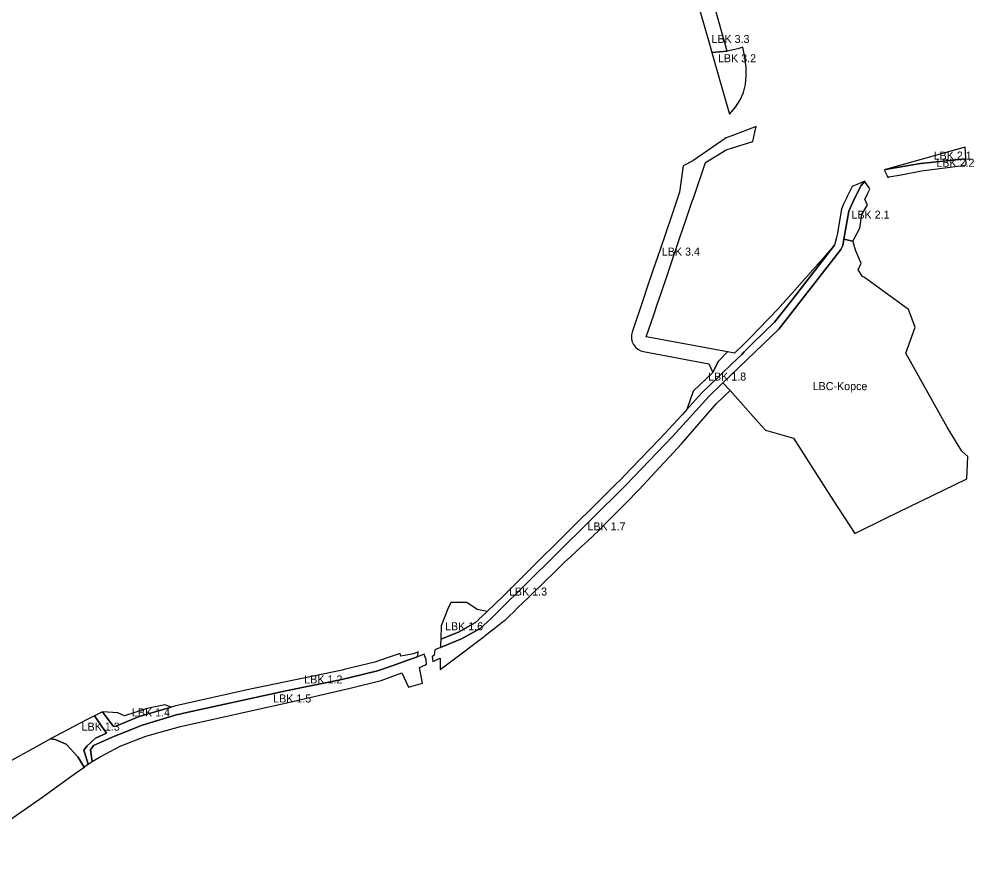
# Model space of a CAD drawing. Extents: x -535894 to -532748, y -1165802 to -1163647.
# Drawn here: x -534673 to -533719, y -1165546 to -1164715 of the extents above; entities that cross this region are included whole.
import ezdxf

# ---------------------------------------------------------------- set-up
doc = ezdxf.new("R2010")
doc.units = 0
for name, color, linetype in [('Level 16', 7, 'Continuous'), ('Level 19', 7, 'Continuous'), ('Level 20', 7, 'Continuous')]:
    doc.layers.add(name, color=color, linetype=linetype)

msp = doc.modelspace()

# ---------------------------------------------------------------- linework, layer by layer
at = {"layer": 'Level 16'}
msp.add_lwpolyline([(-533837.94, -1165228.09), (-533806.07, -1165212.59), (-533726.09, -1165173.68), (-533724.81, -1165151.41), (-533730.88, -1165145.85), (-533745.52, -1165122.1), (-533766.31, -1165084.95), (-533786.95, -1165048.06), (-533777.72, -1165022.03), (-533784.18, -1165004.34), (-533828.25, -1164972.65), (-533830.03, -1164971.49), (-533834.67, -1164964.81), (-533831.57, -1164958.17), (-533833.05, -1164954.72), (-533837.05, -1164945.36), (-533838.84, -1164939.32), (-533839.74, -1164936.26), (-533848.68, -1164934.44), (-533849.69, -1164940.46), (-533851.83, -1164944.65), (-533913.79, -1165024.04), (-533969.7, -1165077.78), (-533962.53, -1165085.32), (-533934.45, -1165116.87), (-533927.15, -1165125.06), (-533899.27, -1165133.08), (-533859.04, -1165195.4)], close=True, dxfattribs=at)
at = {"layer": 'Level 19'}
for points in [[(-533965.28, -1164746.51), (-533980.66, -1164747.97), (-533974.92, -1164767.93), (-533963.1, -1164809.55), (-533956.94, -1164802.51), (-533952.29, -1164795.25), (-533949.05, -1164787.68), (-533947.08, -1164779.74), (-533946.27, -1164771.35), (-533946.51, -1164762.43), (-533947.67, -1164752.91), (-533949.63, -1164742.72), (-533954.82, -1164744.13)], [(-533772.11, -1164858.69), (-533807.19, -1164864.79), (-533808.26, -1164865.36), (-533807.83, -1164866.32), (-533805.67, -1164871.11), (-533804.97, -1164872.65), (-533803.9, -1164872.2), (-533791.44, -1164869.9), (-533771.09, -1164866.14), (-533747.79, -1164863), (-533732.38, -1164860.92), (-533728.63, -1164860.41), (-533726.94, -1164860.18), (-533726.73, -1164859.25), (-533726.9, -1164854), (-533727.16, -1164854.1)], [(-533838.18, -1164893.83), (-533843.98, -1164906.47), (-533848.68, -1164934.44), (-533839.74, -1164936.26), (-533832.91, -1164923.14), (-533831.01, -1164909.18), (-533825.11, -1164900.3), (-533827.81, -1164894.29), (-533825.28, -1164889.29), (-533825.17, -1164889.09), (-533822.83, -1164884.29), (-533823.63, -1164883.1), (-533827.39, -1164877.5), (-533827.73, -1164876.4), (-533831.54, -1164880.79)], [(-533962.53, -1165085.32), (-533969.7, -1165077.78), (-533971.79, -1165079.79), (-533983.52, -1165091.15), (-534019.59, -1165130.92), (-534066.72, -1165179.82), (-534136.8, -1165249.37), (-534194.29, -1165306.12), (-534200.89, -1165312.54), (-534205.31, -1165316.61), (-534212.27, -1165323.02), (-534230.69, -1165333.38), (-534251.77, -1165341.96), (-534257.49, -1165344.29), (-534257.97, -1165349.66), (-534259.96, -1165351.32), (-534259.48, -1165355.88), (-534252.01, -1165352.47), (-534252.23, -1165361.54), (-534251.99, -1165363.99), (-534244.32, -1165358.18), (-534208.23, -1165330.82), (-534207.06, -1165329.91), (-534201.15, -1165325.32), (-534195.4, -1165320.86), (-534189.75, -1165316.48), (-534186.9, -1165314.27), (-534183.78, -1165311.24), (-534178, -1165305.62), (-534174.7, -1165302.41), (-534169.57, -1165297.42), (-534163.98, -1165291.99), (-534158.49, -1165286.65), (-534151.99, -1165280.33), (-534145.91, -1165274.41), (-534140, -1165268.66), (-534133.62, -1165262.47), (-534128.78, -1165257.75), (-534128.1, -1165257.13), (-534121.92, -1165251.44), (-534116.12, -1165246.09), (-534110.88, -1165241.27), (-534105.03, -1165235.88), (-534098.91, -1165230.23), (-534093.73, -1165225.02), (-534088.44, -1165219.7), (-534083.69, -1165214.91), (-534080.31, -1165211.51), (-534069.42, -1165200.54), (-534066.63, -1165197.75), (-534062.36, -1165193.44), (-534057.5, -1165188.56), (-534053.42, -1165184.18), (-534033.26, -1165162.58), (-534022.96, -1165151.54), (-534010.91, -1165138.64), (-533976.02, -1165098.2)], [(-534598.29, -1165439.76), (-534601.36, -1165444.1), (-534599.87, -1165455.71), (-534591.82, -1165451.2), (-534571.82, -1165440.57), (-534546.3, -1165430.52), (-534511.63, -1165420.88), (-534404.04, -1165396.72), (-534341.94, -1165382.62), (-534311.13, -1165374.91), (-534290.38, -1165367.27), (-534283.61, -1165381.53), (-534269.9, -1165377.58), (-534272.9, -1165362.02), (-534267.32, -1165359.47), (-534265.74, -1165358.75), (-534266.24, -1165354.33), (-534268.13, -1165348.62), (-534274.64, -1165351.27), (-534284.53, -1165354.73), (-534300.23, -1165360.21), (-534314.72, -1165365.27), (-534327.1, -1165368.26), (-534344.67, -1165372.49), (-534347.57, -1165373.21), (-534350.42, -1165373.76), (-534406.37, -1165385.09), (-534509.97, -1165407.93), (-534512.18, -1165408.41), (-534514.4, -1165408.9), (-534549.73, -1165419.5), (-534554.75, -1165421.51), (-534567.01, -1165426.39), (-534577.5, -1165430.58)], [(-534578.84, -1165420.53), (-534577.13, -1165420.74), (-534568.84, -1165417.43), (-534552.7, -1165411), (-534520.7, -1165401.39), (-534527.22, -1165399.28), (-534544.87, -1165402.87), (-534557.01, -1165406.86), (-534567.43, -1165410.29), (-534570.57, -1165408.93), (-534574.28, -1165407.33), (-534589.33, -1165406.05), (-534585.71, -1165411.05), (-534584.33, -1165412.96)], [(-534614.06, -1165451.06), (-534607.91, -1165461.42), (-534605.28, -1165459.52), (-534603.88, -1165458.54), (-534607.55, -1165446.4), (-534608.12, -1165444.51), (-534604.65, -1165440.1), (-534601.57, -1165437.17), (-534599.52, -1165435.21), (-534596.58, -1165432.42), (-534585.47, -1165427.37), (-534592.44, -1165417.51), (-534593.89, -1165415.47), (-534597.58, -1165410.25), (-534603.53, -1165413.28), (-534612.41, -1165417.8), (-534641.32, -1165433.01), (-534636.67, -1165433.92), (-534625.81, -1165438.39)]]:
    msp.add_lwpolyline(points, close=True, dxfattribs=at)
for points in [[(-533990.61, -1165087.81), (-533974.83, -1165072.38), (-533971.32, -1165069), (-533960.95, -1165059.02), (-533950.89, -1165049.34), (-533948.25, -1165046.8), (-533939.32, -1165037.78), (-533917.98, -1165017.22), (-533902.83, -1164997.81), (-533898.22, -1164991.91), (-533884.32, -1164974.09), (-533870.47, -1164956.34), (-533858.16, -1164940.26), (-533872.1, -1164956.08), (-533887.6, -1164973.66), (-533903.09, -1164991.22), (-533909.61, -1164998.62), (-533914.87, -1165004.11), (-533933.76, -1165023.78), (-533941.12, -1165031.45), (-533943.27, -1165033.69), (-533949.19, -1165039.53), (-533958, -1165048.21), (-533964.89, -1165046.93), (-533974.3, -1165056.33), (-533979.67, -1165067.29), (-533999.48, -1165086.16), (-534005.54, -1165104.27), (-533990.61, -1165087.81)], [(-534205.1, -1165305.99), (-534215.31, -1165304.06), (-534225.42, -1165296.87), (-534241.33, -1165297.17), (-534244.31, -1165303.28), (-534251.27, -1165320.44), (-534251.58, -1165333.78), (-534233.95, -1165326.61), (-534216.74, -1165316.93), (-534213.98, -1165314.34), (-534213.44, -1165313.82), (-534206.83, -1165307.61), (-534205.1, -1165305.99)]]:
    msp.add_lwpolyline(points, dxfattribs=at)
at = {"layer": 'Level 20'}
for points in [[(-533992.01, -1164708.4), (-533983.41, -1164738.37), (-533980.66, -1164747.97), (-533965.28, -1164746.51), (-533976.64, -1164706.23), (-533978.18, -1164703.55), (-533986.32, -1164682.27), (-533991.85, -1164679.44), (-533997.19, -1164688.03), (-533998.16, -1164689.6), (-534004.08, -1164694.94), (-533996, -1164692.7)], [(-533966.36, -1164833.16), (-533999.79, -1164855.92), (-534009.46, -1164861.21), (-534012.98, -1164887.4), (-534020.8, -1164910.38), (-534027.08, -1164928.91), (-534032.81, -1164945.75), (-534039.22, -1164964.63), (-534045.9, -1164984.32), (-534048.72, -1164992.61), (-534060.38, -1165026.98), (-534061.04, -1165029.85), (-534061.12, -1165033.01), (-534060.49, -1165036.27), (-534059.11, -1165039.38), (-534057.07, -1165042.1), (-534054.54, -1165044.24), (-534051.75, -1165045.72), (-534048.92, -1165046.54), (-533983.72, -1165058.68), (-533979.67, -1165067.29), (-533974.3, -1165056.33), (-533964.89, -1165046.93), (-534046.17, -1165031.8), (-534038.74, -1165009.88), (-534034.52, -1164997.43), (-534031.7, -1164989.14), (-534025.02, -1164969.45), (-534018.61, -1164950.58), (-534012.88, -1164933.73), (-534006.6, -1164915.2), (-534000.56, -1164897.43), (-533998.79, -1164892.25), (-533986.98, -1164857.88), (-533966.45, -1164845.14), (-533960.22, -1164843.18), (-533939.82, -1164836.77), (-533937.75, -1164827.32), (-533936.53, -1164821.76), (-533960.78, -1164831.03)], [(-534592.44, -1165417.51), (-534585.47, -1165427.37), (-534596.58, -1165432.42), (-534599.52, -1165435.21), (-534601.57, -1165437.17), (-534604.65, -1165440.1), (-534608.12, -1165444.51), (-534607.55, -1165446.4), (-534603.88, -1165458.54), (-534599.87, -1165455.71), (-534601.36, -1165444.1), (-534598.29, -1165439.76), (-534577.5, -1165430.58), (-534567.01, -1165426.39), (-534554.75, -1165421.51), (-534549.73, -1165419.5), (-534514.4, -1165408.9), (-534512.18, -1165408.41), (-534509.97, -1165407.93), (-534406.37, -1165385.09), (-534350.42, -1165373.76), (-534347.57, -1165373.21), (-534344.67, -1165372.49), (-534327.1, -1165368.26), (-534314.72, -1165365.27), (-534300.23, -1165360.21), (-534284.53, -1165354.73), (-534274.64, -1165351.27), (-534274.2, -1165347.69), (-534274.04, -1165346.4), (-534275.59, -1165346.89), (-534279.12, -1165348.18), (-534291.43, -1165350.78), (-534292.02, -1165347.81), (-534304.23, -1165352.07), (-534317.27, -1165356.63), (-534348.18, -1165364.09), (-534349.96, -1165364.5), (-534444.99, -1165384.39), (-534513.15, -1165399.41), (-534517.58, -1165400.46), (-534520.7, -1165401.39), (-534552.7, -1165411), (-534568.84, -1165417.43), (-534577.13, -1165420.74), (-534578.84, -1165420.53), (-534584.33, -1165412.96), (-534585.71, -1165411.05), (-534589.33, -1165406.05), (-534597.58, -1165410.25), (-534593.89, -1165415.47)]]:
    msp.add_lwpolyline(points, close=True, dxfattribs=at)
for points in [[(-533739.47, -1164845.64), (-533807.19, -1164864.79), (-533772.11, -1164858.69), (-533727.16, -1164854.1), (-533726.9, -1164854), (-533727.12, -1164847.21), (-533727.67, -1164842.3), (-533739.47, -1164845.64)], [(-533849.69, -1164940.46), (-533848.68, -1164934.44), (-533843.98, -1164906.47), (-533838.18, -1164893.83), (-533831.54, -1164880.79), (-533827.73, -1164876.4), (-533840.36, -1164881.6), (-533845.18, -1164891.1), (-533846.25, -1164893.43), (-533849.34, -1164900.16), (-533851.21, -1164904.25), (-533855.51, -1164929.84), (-533856.25, -1164932.75), (-533858.16, -1164940.26), (-533870.47, -1164956.34), (-533884.32, -1164974.09), (-533898.22, -1164991.91), (-533902.83, -1164997.81), (-533917.98, -1165017.22), (-533939.32, -1165037.78), (-533948.25, -1165046.8), (-533950.89, -1165049.34), (-533960.95, -1165059.02), (-533971.32, -1165069), (-533974.83, -1165072.38), (-533990.61, -1165087.81), (-534005.54, -1165104.27), (-534010.38, -1165109.6), (-534032.62, -1165133.64), (-534061.51, -1165163.61), (-534072.06, -1165174.55), (-534075.93, -1165178.39), (-534078.56, -1165180.99), (-534081.18, -1165183.6), (-534101.59, -1165203.84), (-534114.18, -1165216.32), (-534139.47, -1165241.41), (-534149.08, -1165250.94), (-534189.23, -1165290.59), (-534205.1, -1165305.99), (-534206.83, -1165307.61), (-534213.44, -1165313.82), (-534213.98, -1165314.34), (-534216.74, -1165316.93), (-534233.95, -1165326.61), (-534251.58, -1165333.78), (-534251.69, -1165338.72), (-534251.77, -1165341.96), (-534230.69, -1165333.38), (-534212.27, -1165323.02), (-534205.31, -1165316.61), (-534200.89, -1165312.54), (-534194.29, -1165306.12), (-534136.8, -1165249.37), (-534066.72, -1165179.82), (-534019.59, -1165130.92), (-533983.52, -1165091.15), (-533971.79, -1165079.79), (-533969.7, -1165077.78), (-533913.79, -1165024.04), (-533851.83, -1164944.65), (-533849.69, -1164940.46)], [(-534728.46, -1165546.03), (-534648.91, -1165491.07), (-534614.01, -1165465.83), (-534611.57, -1165464.07), (-534607.91, -1165461.42), (-534614.06, -1165451.06), (-534625.81, -1165438.39), (-534636.67, -1165433.92), (-534641.32, -1165433.01), (-534646.15, -1165435.68), (-534721.71, -1165477.48)]]:
    msp.add_lwpolyline(points, dxfattribs=at)

# ---------------------------------------------------------------- texts
at = {"layer": 'Level 16'}
msp.add_text('LBC-Kopce', height=8, dxfattribs=at).set_placement((-533880, -1165085))
at = {"layer": 'Level 19'}
for s, p in [('LBK 3.2', (-533974.55, -1164757.66)), ('LBK 2.2', (-533756.4, -1164862.03)), ('LBK 2.1', (-533841.22, -1164913.84)), ('LBK 1.8', (-533984.5, -1165075.43)), ('LBK 1.7', (-534105, -1165225)), ('LBK 1.6', (-534247.28, -1165324.74)), ('LBK 1.5', (-534418.94, -1165396.87)), ('LBK 1.4', (-534560.04, -1165410.79)), ('LBK 1.3', (-534610.33, -1165425))]:
    msp.add_text(s, height=8, dxfattribs=at).set_placement(p)
at = {"layer": 'Level 20'}
for s, p in [('LBK 3.3', (-533981.13, -1164738.37)), ('LBK 2.1', (-533759.1, -1164854.79)), ('LBK 3.4', (-534030.71, -1164950.7)), ('LBK 1.3', (-534183.38, -1165290.09)), ('LBK 1.2', (-534387.87, -1165377.84))]:
    msp.add_text(s, height=8, dxfattribs=at).set_placement(p)

doc.saveas('drawing.dxf')
